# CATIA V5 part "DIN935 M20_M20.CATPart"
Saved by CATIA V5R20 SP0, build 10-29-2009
Part number: DIN935 M20_M20
Revision: ANY
Definition: UNKNOWN
Nomenclature: DIN935 M20_M20
Source: Unknown
Bounding box of the stored display mesh (mm): x -15 to 15, y -17.321 to 17.321, z 0 to 22
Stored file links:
  C:\Users\Utente\Desktop\IO LAVORO\3D X SITO CF\X 3D SITO CF 27-09-2020\740T\740T-20\DIN935 M20_M20.CATPart
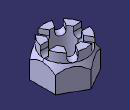
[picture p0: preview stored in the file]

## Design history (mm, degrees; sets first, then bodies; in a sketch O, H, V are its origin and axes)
Body1 "NONE" (main body)
  Solid1: solid without history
